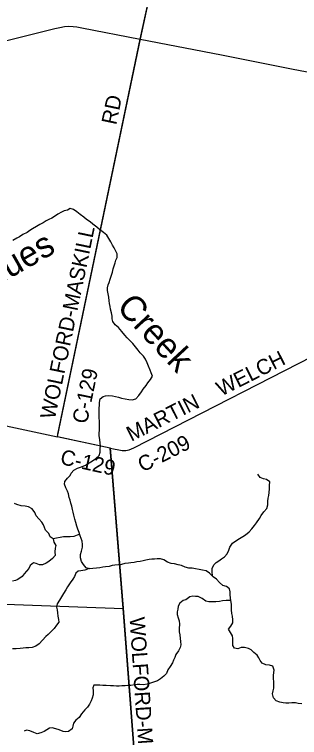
# Model space of a CAD drawing. Extents: x 0 to 34, y 0 to 22.
# Drawn here: x 7.582 to 8.115, y 15.21 to 16.562 of the extents above; entities that cross this region are included whole.
import ezdxf

# ---------------------------------------------------------------- set-up
doc = ezdxf.new("R2010")
doc.units = 0
for name, color, linetype in [('GM_X_Corporation', 7, 'Continuous'), ('GM_X_County_Road', 7, 'Continuous'), ('GM_X_County_Road_Text', 7, 'Continuous'), ('GM_X_Minor_River', 7, 'Continuous'), ('GM_X_Minor_River_Text', 7, 'Continuous'), ('GM_X_State_Route', 7, 'Continuous'), ('GM_X_Township_Road', 7, 'Continuous')]:
    doc.layers.add(name, color=color, linetype=linetype)

msp = doc.modelspace()

# ---------------------------------------------------------------- linework, layer by layer
at = {"layer": 'GM_X_Corporation'}
msp.add_lwpolyline([(8.0146, 17.4385), (8.0061, 17.4015), (7.9483, 17.1186), (7.8667, 16.7439), (7.8171, 16.5163), (7.6624, 15.7725), (7.761, 15.7513), (7.7853, 15.4515), (7.8145, 15.0705), (8.0549, 15.0964), (8.0668, 14.9397), (8.0887, 14.5411), (8.0986, 14.3711), (8.2117, 14.3797), (8.4217, 14.3956), (8.5553, 14.4065), (8.6255, 14.4123), (8.6725, 14.4163), (8.8777, 14.4334), (8.8814, 14.4337), (8.9, 14.4352), (8.9, 17.4353)], dxfattribs=at)
at = {"layer": 'GM_X_County_Road'}
for points in [[(7.6636, 15.7772), (7.8172, 16.516), (7.8668, 16.7436), (7.8901, 16.8507)], [(7.7611, 15.751), (7.7834, 15.7467), (7.7905, 15.7464), (7.7966, 15.7477), (7.8052, 15.7514), (8.1898, 15.9485), (8.203, 15.9567)], [(7.7611, 15.751), (7.6625, 15.7723), (7.6636, 15.7772)], [(7.8544, 14.3533), (7.852, 14.4013), (7.8426, 14.5915), (7.8336, 14.7611), (7.8245, 14.909), (7.8221, 14.9464), (7.817, 15.0305), (7.8146, 15.0702), (7.7855, 15.4513), (7.7611, 15.751)], [(6.888, 15.4237), (7.3443, 15.4647), (7.3761, 15.465), (7.4099, 15.4642), (7.5307, 15.4607), (7.7855, 15.4513)]]:
    msp.add_lwpolyline(points, dxfattribs=at)
at = {"layer": 'GM_X_Minor_River'}
for points in [[(7.815, 15.8494), (7.82, 15.8562), (7.823, 15.8611), (7.8282, 15.868), (7.8318, 15.8729), (7.8367, 15.8795), (7.84, 15.8856), (7.8375, 15.892), (7.8357, 15.897), (7.8329, 15.9042), (7.8304, 15.9106), (7.827, 15.9173), (7.8234, 15.9232), (7.8172, 15.9293), (7.8132, 15.934), (7.8082, 15.9405), (7.8036, 15.9466), (7.7978, 15.9523), (7.7929, 15.9573), (7.7887, 15.962), (7.7827, 15.9694), (7.7766, 15.9765), (7.7704, 15.9814), (7.7661, 15.9877), (7.7648, 15.9928), (7.7646, 15.9976), (7.7635, 16.0039), (7.762, 16.0109), (7.7609, 16.0156), (7.7599, 16.0213), (7.7594, 16.0266), (7.7588, 16.0333), (7.7575, 16.0397), (7.7559, 16.046), (7.7563, 16.0509), (7.7576, 16.0561), (7.759, 16.061), (7.7609, 16.0667), (7.7634, 16.0744), (7.7653, 16.0799), (7.7668, 16.0862), (7.7686, 16.0917), (7.7705, 16.0974), (7.772, 16.1023), (7.7741, 16.1078), (7.7745, 16.1141), (7.7689, 16.1255), (7.7655, 16.1306), (7.7623, 16.1365), (7.7587, 16.1431), (7.7549, 16.1494), (7.7487, 16.1544), (7.7413, 16.1599), (7.736, 16.1641), (7.7287, 16.1698), (7.7238, 16.174), (7.717, 16.1786), (7.712, 16.183), (7.7054, 16.1877), (7.699, 16.1929), (7.6924, 16.1975), (7.6863, 16.199), (7.6816, 16.196), (7.6751, 16.1945), (7.67, 16.1922), (7.6637, 16.1883), (7.659, 16.1854), (7.6519, 16.1811), (7.6466, 16.1787), (7.6417, 16.176), (7.636, 16.1722), (7.6301, 16.169), (7.6236, 16.1653), (7.6158, 16.1609), (7.6109, 16.1577), (7.6061, 16.1545), (7.5983, 16.1502), (7.5921, 16.1464), (7.5869, 16.1438), (7.5791, 16.1394)], [(7.8813, 15.5347), (7.8751, 15.5351), (7.8683, 15.538), (7.8613, 15.5424), (7.855, 15.5439), (7.8491, 15.5438), (7.8438, 15.5436), (7.8391, 15.5432), (7.834, 15.5429), (7.8275, 15.5416), (7.8228, 15.5402), (7.8171, 15.5391), (7.8108, 15.5382), (7.8061, 15.5375), (7.8, 15.5365), (7.7952, 15.536), (7.7886, 15.5351), (7.7822, 15.5336), (7.7765, 15.5328), (7.77, 15.5321), (7.7651, 15.5314), (7.759, 15.53), (7.7526, 15.5291), (7.7476, 15.5284), (7.7417, 15.5271), (7.7355, 15.5263), (7.729, 15.5262), (7.7224, 15.5256), (7.7162, 15.527), (7.7112, 15.5335), (7.7079, 15.539), (7.7056, 15.5458), (7.706, 15.5519), (7.7077, 15.5581), (7.7097, 15.5659), (7.7097, 15.5707), (7.7086, 15.5769), (7.7069, 15.5821), (7.7052, 15.5868), (7.7031, 15.5936), (7.7009, 15.5997), (7.6992, 15.6054), (7.6973, 15.6117), (7.6949, 15.6185), (7.6932, 15.6258), (7.6921, 15.6314), (7.6911, 15.6364), (7.6893, 15.6423), (7.6878, 15.6482), (7.6865, 15.6537), (7.6848, 15.6586), (7.6831, 15.6656), (7.6814, 15.6706), (7.6782, 15.6767), (7.676, 15.6839), (7.6767, 15.6886), (7.6817, 15.6951), (7.6865, 15.6996), (7.6886, 15.7043), (7.6935, 15.71), (7.7003, 15.7138), (7.7076, 15.716), (7.715, 15.7194), (7.7218, 15.7238), (7.7283, 15.7271), (7.7344, 15.7319), (7.7408, 15.7372), (7.7424, 15.7438), (7.7426, 15.7502), (7.7428, 15.755), (7.7426, 15.7605), (7.7417, 15.7673), (7.7408, 15.774), (7.7408, 15.7791), (7.741, 15.7844), (7.7414, 15.7897), (7.7414, 15.7948), (7.7411, 15.8021), (7.7409, 15.8072), (7.7407, 15.8148), (7.7406, 15.8197), (7.7408, 15.8254), (7.741, 15.8317), (7.741, 15.8366), (7.7422, 15.843), (7.7479, 15.8476), (7.7526, 15.8487), (7.7589, 15.8494), (7.7653, 15.8486), (7.771, 15.8473), (7.7765, 15.8461), (7.7826, 15.8444), (7.789, 15.8434), (7.7962, 15.8421), (7.8025, 15.8415), (7.8091, 15.8435), (7.815, 15.8494)], [(7.9521, 15.5123), (7.9518, 15.5197), (7.952, 15.5259), (7.9545, 15.5327), (7.9594, 15.5375), (7.9642, 15.5405), (7.9693, 15.5439), (7.9745, 15.5475), (7.9798, 15.5531), (7.9828, 15.5603), (7.985, 15.566), (7.9899, 15.5732), (7.9962, 15.5776), (8.0028, 15.5823), (8.0089, 15.5859), (8.014, 15.5891), (8.0207, 15.5947), (8.026, 15.6002), (8.0306, 15.6061), (8.0344, 15.6114), (8.0399, 15.6192), (8.0434, 15.625), (8.0483, 15.6318), (8.0539, 15.6383), (8.0556, 15.6451), (8.0558, 15.6519), (8.0566, 15.6576), (8.0574, 15.6627), (8.058, 15.668), (8.0585, 15.6747), (8.0588, 15.6813), (8.0594, 15.688), (8.0529, 15.6927), (8.0478, 15.6939), (8.0412, 15.696), (8.0372, 15.7025)], [(7.7042, 15.5902), (7.6997, 15.5885), (7.6932, 15.5861), (7.6864, 15.5855), (7.6811, 15.5852), (7.6737, 15.585), (7.668, 15.5839), (7.6612, 15.5826), (7.6545, 15.5817), (7.6492, 15.5853), (7.6464, 15.5916), (7.6404, 15.5975), (7.6383, 15.6024), (7.6366, 15.6076), (7.6334, 15.6125), (7.6278, 15.6186), (7.6228, 15.6247), (7.6202, 15.6308), (7.6153, 15.6376), (7.6085, 15.6412), (7.6023, 15.6426), (7.5952, 15.6432), (7.5871, 15.6455), (7.5822, 15.6478)], [(7.6545, 15.5817), (7.6562, 15.575), (7.6596, 15.5689), (7.6585, 15.564), (7.6579, 15.5574), (7.6582, 15.5505), (7.6535, 15.5447), (7.6468, 15.5392), (7.6419, 15.5358), (7.6348, 15.5326), (7.6293, 15.5328), (7.6227, 15.5355), (7.6178, 15.5363), (7.6119, 15.5314), (7.609, 15.526), (7.605, 15.5209), (7.6006, 15.516), (7.5965, 15.5111), (7.5889, 15.5054), (7.5841, 15.5037), (7.5788, 15.5021)], [(7.722, 15.5257), (7.7139, 15.5228), (7.7065, 15.5217), (7.7017, 15.521), (7.697, 15.5172), (7.6947, 15.5109), (7.6916, 15.506), (7.6865, 15.4992), (7.6815, 15.4914), (7.6781, 15.4863), (7.6743, 15.4793), (7.6703, 15.4729), (7.6663, 15.4666), (7.6621, 15.46), (7.6611, 15.4539), (7.6624, 15.4484), (7.663, 15.4431), (7.6637, 15.4366), (7.6646, 15.4306), (7.665, 15.4258), (7.661, 15.4198), (7.6564, 15.4137), (7.6518, 15.4088), (7.6456, 15.4025), (7.6408, 15.3986), (7.6345, 15.392), (7.6284, 15.3853), (7.6222, 15.3808), (7.6153, 15.378), (7.6093, 15.3778), (7.6034, 15.3775), (7.5985, 15.3771), (7.5931, 15.3764), (7.5857, 15.376), (7.5787, 15.3758)], [(8.1123, 15.2737), (8.1072, 15.2748), (8.1003, 15.2746), (8.0946, 15.2741), (8.0893, 15.2741), (8.0846, 15.2751), (8.0782, 15.2759), (8.0713, 15.2784), (8.066, 15.2839), (8.0644, 15.2919), (8.0659, 15.297), (8.0667, 15.3025), (8.0671, 15.3072), (8.0667, 15.3144), (8.0664, 15.3198), (8.066, 15.3258), (8.067, 15.3313), (8.0676, 15.3361), (8.0651, 15.3433), (8.0587, 15.3454), (8.052, 15.3458), (8.0452, 15.3489), (8.0415, 15.354), (8.0388, 15.3588), (8.0356, 15.3637), (8.0294, 15.3692), (8.0243, 15.3738), (8.0194, 15.3767), (8.0123, 15.3784), (8.0061, 15.3784), (7.9994, 15.3758), (7.9934, 15.377), (7.9906, 15.3819), (7.9906, 15.3891), (7.9904, 15.3952), (7.9897, 15.4001), (7.9861, 15.4062), (7.9819, 15.4127), (7.9863, 15.4184), (7.9903, 15.4246), (7.9905, 15.4297), (7.9894, 15.437), (7.9887, 15.4421), (7.9879, 15.4489), (7.9878, 15.4539), (7.9876, 15.4592), (7.9863, 15.466), (7.9861, 15.4708), (7.9856, 15.4772), (7.9852, 15.4821), (7.9843, 15.4878), (7.9782, 15.4926), (7.9718, 15.4945), (7.9654, 15.4997), (7.9599, 15.506), (7.9538, 15.5107), (7.947, 15.517), (7.9402, 15.5214), (7.9336, 15.5231), (7.9274, 15.5243), (7.9205, 15.5253), (7.9143, 15.5266), (7.908, 15.5265), (7.901, 15.5282), (7.8942, 15.5313), (7.8883, 15.5326), (7.8813, 15.5347)], [(7.9863, 15.4664), (7.9781, 15.466), (7.9711, 15.4653), (7.9656, 15.4644), (7.9586, 15.4635), (7.9455, 15.4635), (7.9398, 15.4648), (7.9328, 15.4696), (7.9258, 15.4734), (7.9205, 15.4738), (7.9158, 15.4742), (7.9097, 15.4733), (7.9025, 15.4676), (7.8978, 15.466), (7.8911, 15.4612), (7.8882, 15.4554), (7.8873, 15.4499), (7.8865, 15.4447), (7.8865, 15.4398), (7.8884, 15.4337), (7.8902, 15.4284), (7.8908, 15.4216), (7.8902, 15.4138), (7.8902, 15.4077), (7.8913, 15.4022), (7.892, 15.3954), (7.8924, 15.3893), (7.8931, 15.383), (7.8921, 15.3783), (7.8887, 15.372), (7.8841, 15.3652), (7.882, 15.3597), (7.8792, 15.3548), (7.8774, 15.3493), (7.8731, 15.3425), (7.8689, 15.3362), (7.8666, 15.3294), (7.8616, 15.3249), (7.8552, 15.3196), (7.8495, 15.3162), (7.8421, 15.3134), (7.8365, 15.3117), (7.8305, 15.3098), (7.8233, 15.3085), (7.8168, 15.3089), (7.8117, 15.3091), (7.8068, 15.3082), (7.7996, 15.3074), (7.7941, 15.3073), (7.7893, 15.3069), (7.7829, 15.3069), (7.7781, 15.3062), (7.773, 15.3062), (7.7677, 15.3064), (7.7615, 15.3066), (7.7535, 15.3074), (7.7474, 15.3073), (7.7421, 15.3077), (7.737, 15.3081), (7.7307, 15.3077), (7.7285, 15.3026), (7.7292, 15.2975), (7.7294, 15.29), (7.7278, 15.2836), (7.7259, 15.2787), (7.7227, 15.2724), (7.7187, 15.2667), (7.7139, 15.262), (7.7074, 15.2543), (7.7032, 15.2476), (7.6968, 15.2427), (7.6926, 15.237), (7.6912, 15.231), (7.6899, 15.2262), (7.6832, 15.2213), (7.6783, 15.2206), (7.6732, 15.2212), (7.6662, 15.2242), (7.6597, 15.2261), (7.6527, 15.2283), (7.648, 15.2273), (7.6431, 15.2245), (7.6379, 15.2209), (7.6319, 15.2188), (7.625, 15.2168), (7.6184, 15.2191), (7.6114, 15.2227), (7.6051, 15.2237), (7.6004, 15.2216)], [(8.1189, 15.2731), (8.1123, 15.2737)]]:
    msp.add_lwpolyline(points, dxfattribs=at)
at = {"layer": 'GM_X_State_Route'}
for points in [[(6.6919, 16.2947), (7.1249, 16.4025), (7.6578, 16.5356), (7.6669, 16.5378), (7.6758, 16.5395), (7.6836, 16.54), (7.6922, 16.5394), (7.699, 16.5386), (7.7081, 16.5372), (7.8172, 16.516)], [(7.8172, 16.516), (7.9689, 16.4862), (8.1033, 16.4594), (8.2346, 16.4347), (8.3418, 16.4142), (8.3651, 16.41), (8.4043, 16.4024), (8.5045, 16.3815), (8.5608, 16.3695), (8.6381, 16.3543), (8.7061, 16.3412), (8.7832, 16.3286), (8.9, 16.3104)]]:
    msp.add_lwpolyline(points, dxfattribs=at)
at = {"layer": 'GM_X_Township_Road'}
msp.add_lwpolyline([(6.7711, 15.9427), (6.8449, 15.9325), (6.858, 15.931), (6.8695, 15.9303), (6.8802, 15.9302), (6.8952, 15.9305), (6.9021, 15.9305), (6.908, 15.9302), (6.9162, 15.929), (6.9352, 15.9253), (7.0463, 15.9032), (7.2361, 15.8626), (7.4879, 15.8094), (7.6625, 15.7723)], dxfattribs=at)

# ---------------------------------------------------------------- texts
at = {"layer": 'GM_X_County_Road_Text'}
for s, height, rotation, p in [('RD', 0.02841, 78.112, (7.7723, 16.3542)), ('WOLFORD-MASKILL', 0.028409, 78.2461, (7.6577, 15.8037)), ('WELCH', 0.02841, 26.8165, (7.9686, 15.8473)), ('C-129', 0.02841, 78.3663, (7.7178, 15.7953)), ('MARTIN', 0.02841, 26.7997, (7.8007, 15.7627)), ('C-209', 0.02841, 26.8118, (7.8217, 15.7053)), ('C-129', 0.02841, 347.5017, (7.6663, 15.7216)), ('WOLFORD-MASKILL', 0.028409, 273.8893, (7.7973, 15.4343))]:
    msp.add_text(s, height=height, rotation=rotation, dxfattribs=at).set_placement(p)
at = {"layer": 'GM_X_Minor_River_Text'}
for s, rotation, p in [('Blues', 29.6381, (7.5242, 16.0399)), ('Creek', 312.9239, (7.7713, 16.0133))]:
    msp.add_text(s, height=0.04735, rotation=rotation, dxfattribs=at).set_placement(p)

doc.saveas('drawing.dxf')
